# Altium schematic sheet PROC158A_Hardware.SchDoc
size 431 x 279 mm; Date: Not shown in title block; ApprovedBy: Not shown in title block; CheckedBy: Not shown in title block; Author: Not shown in title block; CompanyName: Not shown in title block; Engineer: Not shown in title block; Organization: Not shown in title block; Address1: Not shown in title block; Address2: Not shown in title block; Address3: Not shown in title block; Address4: Not shown in title block; DocumentNumber: 25; Revision: Use project parameter SCH_Rev; SheetNumber: 24; SheetTotal: 24; PageSetup: Record=PageOptions¦CenterHorizontal=True¦CenterVertical=True¦PrintScale=1.00¦XCorrection=1.00¦YCorrection=1.00¦PrintKind=0¦BorderSize=5000000¦LeftOffset=0¦BottomOffset=0¦Orientation=2¦PaperLength=1000¦PaperWidth=1000¦Scale=100¦PaperSource=15¦PrintQuality=600¦MediaType=1¦DitherType=10¦PaperKind=Letter¦PrintScaleMode=1
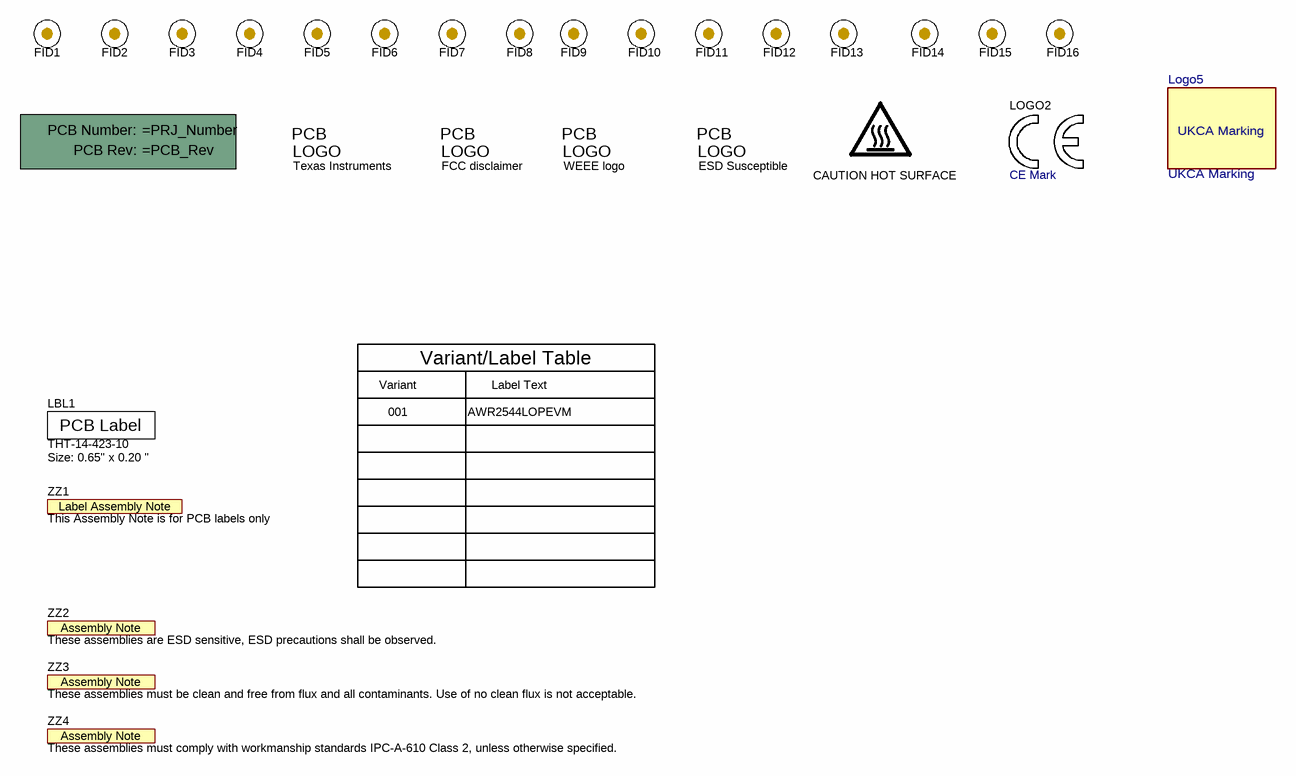
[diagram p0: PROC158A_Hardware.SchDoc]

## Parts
!PCB  Printed Circuit Board  (value not drawn)  (mechanical)
CAUTION_HOT_SURFACE1  CAUTION HOT SURFACE  [IEC_HotSurface_Small]  (no BOM)
ESD_Susceptible1  ESD Susceptible  [ESD_Overlay_Small]  (no BOM)
FID1  Fiducial  [Fiducial10-20]  (value not drawn)  (no BOM)
FID2  Fiducial  [Fiducial10-20]  (value not drawn)  (no BOM)
FID3  Fiducial  [Fiducial10-20]  (value not drawn)  (no BOM)
FID4  Fiducial  [Fiducial10-20]  (value not drawn)  (no BOM)
FID5  Fiducial  [Fiducial10-20]  (value not drawn)  (no BOM)
FID6  Fiducial  [Fiducial10-20]  (value not drawn)  (no BOM)
FID7  Fiducial  [Fiducial10-20]  (value not drawn)  (no BOM)
FID8  Fiducial  [Fiducial10-20]  (value not drawn)  (no BOM)
FID9  Fiducial  [Fiducial10-20]  (value not drawn)  (no BOM)
FID10  Fiducial  [Fiducial10-20]  (value not drawn)  (no BOM)
FID11  Fiducial  [Fiducial10-20]  (value not drawn)  (no BOM)
FID12  Fiducial  [Fiducial10-20]  (value not drawn)  (no BOM)
FID13  Fiducial  [Fiducial10-20]  (value not drawn)  (no BOM)
FID14  Fiducial  [Fiducial10-20]  (value not drawn)  (no BOM)
FID15  Fiducial  [Fiducial10-20]  (value not drawn)  (no BOM)
FID16  Fiducial  [Fiducial10-20]  (value not drawn)  (no BOM)
LBL1  THT-14-423-10  Note: Size: 0.65" x 0.20 "  [Label_650x200]  (no BOM)
Logo1  Texas Instruments  [TI_Stacked_Overlay_Small]  (no BOM)
LOGO2  CE Mark  [CE_Mark_5mm]  (no BOM)
Logo3  FCC disclaimer  [FCC_disclaimer]  (no BOM)
Logo4  WEEE logo  [WEEE_Minimum]  (no BOM)
Logo5  UKCA Marking  [-UKCA_Filled]
ZZ1  This Assembly Note is for PCB labels only  [AssemblyNoteLabel]  (no BOM)
ZZ2  These assemblies are ESD sensitive, ESD precautions shall be observed.  [AssemblyNote]  (no BOM)
ZZ3  These assemblies must be clean and free from flux and all contaminants. Use of no clean flux is not acceptable.  [AssemblyNote]  (no BOM)
ZZ4  These assemblies must comply with workmanship standards IPC-A-610 Class 2, unless otherwise specified.  [AssemblyNote]  (no BOM)

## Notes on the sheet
- Variant
- Variant/Label Table
- Label Text
- 001
- AWR2544LOPEVM

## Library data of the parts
!PCB = CMP-0003618-2: Manufacturer: Any
CAUTION_HOT_SURFACE1 = CMP-0074837-1: IEC 61010-1 Hot Surface Warning; Library Reference: IEC_HotSurface; SymbolCreator: a0412235
ESD_Susceptible1 = CMP-0074840-1: ESD Susceptible Symbol; Library Reference: Logo; SymbolCreator: a0412235; Lib Reference: ESD_Susceptible
FID1-FID16 = CMP-0077181-1: Fiducial mark.  There is nothing to buy or mount.
LBL1 = CMP-0003625-1: Thermal Transfer Printable Labels, 0.650" W x 0.200" H - 10,000 per roll; Manufacturer: Brady; CompType: Label; Value: xWR2944EVM
Logo1 = CMP-0074838-1: Texas Instrument Corporate Signature; SymbolCreator: a0412235; Lib Reference: TI_Logo; Library Reference: Logo
LOGO2 = CMP-0074844-1: SymbolCreator: a0412235
Logo3 = CMP-0074847-1: FCC_disclaimer; Library Reference: Logo
Logo4 = CMP-0074769-1
Logo5 = CMP-0093808-1: Manufacturer: Texas Instruments
ZZ1 = CMP-0003616-3
ZZ2 = CMP-0077236-1
ZZ3 = CMP-0077237-1
ZZ4 = CMP-0077238-1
